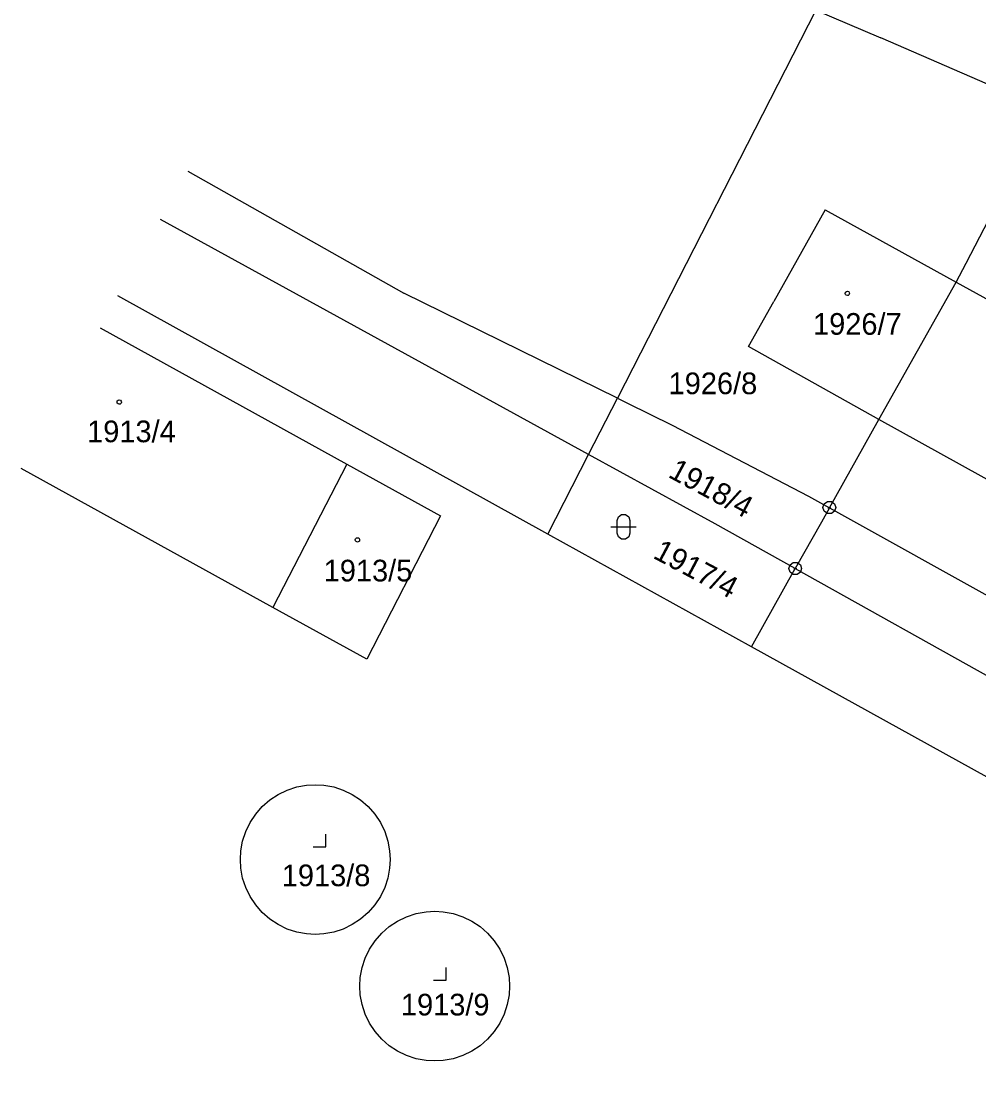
# Model space of a CAD drawing. Extents: x -528274 to -527531, y -1079304 to -1078580.
# Drawn here: x -528058.5 to -527983.4, y -1078819.1 to -1078735.9 of the extents above; entities that cross this region are included whole.
import ezdxf

# ---------------------------------------------------------------- set-up
doc = ezdxf.new("R2010")
doc.units = 0
doc.layers.add('katastrální mapa', color=7, linetype='Continuous')

msp = doc.modelspace()

# ---------------------------------------------------------------- linework, layer by layer
at = {"layer": 'katastrální mapa'}
for p, q in [((-527996.14, -1078735.08), (-528011.72, -1078765.52)), ((-527996.14, -1078735.08), (-527991.06, -1078737.26)), ((-527978.3, -1078742.81), (-527991.06, -1078737.26)), ((-528045.427, -1078747.725), (-528028.47, -1078757.28)), ((-527984.36, -1078754.92), (-527981.87, -1078750.15)), ((-527995.41, -1078750.75), (-527999.45, -1078757.94)), ((-527995.41, -1078750.75), (-527985.15, -1078756.42)), ((-528013.97, -1078769.93), (-528047.547, -1078751.51)), ((-527985.15, -1078756.42), (-527984.36, -1078754.92)), ((-527991.2, -1078767.2), (-527985.15, -1078756.42)), ((-527985.15, -1078756.42), (-527971.57, -1078763.89)), ((-528017.17, -1078776.18), (-528050.904, -1078757.504)), ((-528011.72, -1078765.52), (-528028.47, -1078757.28)), ((-528001.44, -1078761.48), (-527999.45, -1078757.94)), ((-528052.305, -1078760.006), (-528032.94, -1078770.7)), ((-527991.2, -1078767.2), (-528001.44, -1078761.48)), ((-528013.97, -1078769.93), (-528011.72, -1078765.52)), ((-528011.72, -1078765.52), (-528010.91, -1078765.92)), ((-528010.91, -1078765.92), (-528007.43, -1078767.64)), ((-527995.08, -1078774.12), (-527991.2, -1078767.2)), ((-527977.61, -1078774.72), (-527991.2, -1078767.2)), ((-528007.43, -1078767.64), (-527996.71, -1078773.21)), ((-528017.17, -1078776.18), (-528013.97, -1078769.93)), ((-528004.05, -1078775.37), (-528013.97, -1078769.93)), ((-528038.74, -1078781.95), (-528058.488, -1078771.047)), ((-528032.94, -1078770.7), (-528038.74, -1078781.95)), ((-528032.94, -1078770.7), (-528025.59, -1078774.75)), ((-527996.71, -1078773.21), (-527995.08, -1078774.12)), ((-527995.08, -1078774.12), (-527995.71, -1078775.24)), ((-527995.2, -1078774.12), (-527994.96, -1078774.12)), ((-527995.08, -1078774.12), (-527926.64, -1078812.22)), ((-528025.59, -1078774.75), (-528031.36, -1078786)), ((-527997.76, -1078778.89), (-528004.05, -1078775.37)), ((-527995.71, -1078775.24), (-527997.76, -1078778.89)), ((-528001.2, -1078785.02), (-528017.17, -1078776.18)), ((-528001.2, -1078785.02), (-527997.76, -1078778.89)), ((-527997.88, -1078778.89), (-527997.64, -1078778.89)), ((-527997.76, -1078778.89), (-527934.62, -1078814.19)), ((-528031.36, -1078786), (-528038.74, -1078781.95)), ((-527931.92, -1078823.37), (-528001.2, -1078785.02))]:
    msp.add_line(p, q, dxfattribs=at)
for points in [[(-527993.67, -1078757.14), (-527993.57, -1078757.16), (-527993.52, -1078757.25), (-527993.5, -1078757.31), (-527993.52, -1078757.4), (-527993.6, -1078757.47), (-527993.67, -1078757.48), (-527993.76, -1078757.45), (-527993.82, -1078757.39), (-527993.84, -1078757.31), (-527993.82, -1078757.22), (-527993.74, -1078757.15)], [(-528050.8, -1078765.66), (-528050.7, -1078765.68), (-528050.65, -1078765.77), (-528050.63, -1078765.83), (-528050.65, -1078765.92), (-528050.73, -1078765.99), (-528050.8, -1078766), (-528050.89, -1078765.97), (-528050.95, -1078765.91), (-528050.97, -1078765.83), (-528050.95, -1078765.74), (-528050.87, -1078765.67)], [(-527994.93, -1078773.64), (-527994.68, -1078773.82), (-527994.58, -1078774.11), (-527994.68, -1078774.4), (-527994.93, -1078774.58), (-527995.24, -1078774.58), (-527995.49, -1078774.4), (-527995.59, -1078774.11), (-527995.49, -1078773.82), (-527995.24, -1078773.64)], [(-528011.74, -1078775.12), (-528011.64, -1078774.83), (-528011.39, -1078774.65), (-528011.08, -1078774.65), (-528010.83, -1078774.83), (-528010.73, -1078775.12), (-528010.73, -1078776.12), (-528010.83, -1078776.41), (-528011.08, -1078776.59), (-528011.39, -1078776.59), (-528011.64, -1078776.41), (-528011.74, -1078776.12)], [(-528032.11, -1078776.47), (-528032.01, -1078776.49), (-528031.96, -1078776.58), (-528031.94, -1078776.64), (-528031.96, -1078776.73), (-528032.04, -1078776.8), (-528032.11, -1078776.81), (-528032.2, -1078776.78), (-528032.26, -1078776.72), (-528032.28, -1078776.64), (-528032.26, -1078776.55), (-528032.18, -1078776.48)], [(-527997.61, -1078778.41), (-527997.36, -1078778.59), (-527997.26, -1078778.88), (-527997.36, -1078779.17), (-527997.61, -1078779.35), (-527997.92, -1078779.35), (-527998.17, -1078779.17), (-527998.27, -1078778.88), (-527998.17, -1078778.59), (-527997.92, -1078778.41)]]:
    msp.add_lwpolyline(points, close=True, dxfattribs=at)
for points in [[(-528012.24, -1078775.62), (-528010.97, -1078775.62), (-528010.24, -1078775.62)], [(-528035.42, -1078807.59), (-528036.099, -1078807.557), (-528036.872, -1078807.414), (-528037.62, -1078807.169), (-528038.328, -1078806.827), (-528038.983, -1078806.393), (-528039.575, -1078805.875), (-528040.093, -1078805.283), (-528040.527, -1078804.628), (-528040.869, -1078803.92), (-528041.114, -1078803.172), (-528041.257, -1078802.399), (-528041.29, -1078801.72), (-528041.257, -1078801.041), (-528041.114, -1078800.268), (-528040.869, -1078799.52), (-528040.527, -1078798.812), (-528040.093, -1078798.157), (-528039.575, -1078797.565), (-528038.983, -1078797.047), (-528038.328, -1078796.613), (-528037.62, -1078796.271), (-528036.872, -1078796.026), (-528036.099, -1078795.883), (-528035.42, -1078795.85)], [(-528035.42, -1078795.85), (-528034.741, -1078795.883), (-528033.968, -1078796.026), (-528033.22, -1078796.271), (-528032.512, -1078796.613), (-528031.857, -1078797.047), (-528031.265, -1078797.565), (-528030.747, -1078798.157), (-528030.313, -1078798.812), (-528029.971, -1078799.52), (-528029.726, -1078800.268), (-528029.583, -1078801.041), (-528029.55, -1078801.72), (-528029.583, -1078802.399), (-528029.726, -1078803.172), (-528029.971, -1078803.92), (-528030.313, -1078804.628), (-528030.747, -1078805.283), (-528031.265, -1078805.875), (-528031.857, -1078806.393), (-528032.512, -1078806.827), (-528033.22, -1078807.169), (-528033.968, -1078807.414), (-528034.741, -1078807.557), (-528035.42, -1078807.59)], [(-528035.58, -1078800.73), (-528034.58, -1078800.73), (-528034.58, -1078799.73)], [(-528026.05, -1078817.52), (-528026.729, -1078817.487), (-528027.502, -1078817.344), (-528028.25, -1078817.099), (-528028.958, -1078816.757), (-528029.613, -1078816.323), (-528030.205, -1078815.805), (-528030.723, -1078815.213), (-528031.157, -1078814.558), (-528031.499, -1078813.85), (-528031.744, -1078813.102), (-528031.887, -1078812.329), (-528031.92, -1078811.65), (-528031.887, -1078810.971), (-528031.744, -1078810.198), (-528031.499, -1078809.45), (-528031.157, -1078808.742), (-528030.723, -1078808.087), (-528030.205, -1078807.495), (-528029.613, -1078806.977), (-528028.958, -1078806.543), (-528028.25, -1078806.201), (-528027.502, -1078805.956), (-528026.729, -1078805.813), (-528026.05, -1078805.78)], [(-528026.05, -1078805.78), (-528025.371, -1078805.813), (-528024.598, -1078805.956), (-528023.85, -1078806.201), (-528023.142, -1078806.543), (-528022.487, -1078806.977), (-528021.895, -1078807.495), (-528021.377, -1078808.087), (-528020.943, -1078808.742), (-528020.601, -1078809.45), (-528020.356, -1078810.198), (-528020.213, -1078810.971), (-528020.18, -1078811.65), (-528020.213, -1078812.329), (-528020.356, -1078813.102), (-528020.601, -1078813.85), (-528020.943, -1078814.558), (-528021.377, -1078815.213), (-528021.895, -1078815.805), (-528022.487, -1078816.323), (-528023.142, -1078816.757), (-528023.85, -1078817.099), (-528024.598, -1078817.344), (-528025.371, -1078817.487), (-528026.05, -1078817.52)], [(-528026.15, -1078811.18), (-528025.15, -1078811.18), (-528025.15, -1078810.18)]]:
    msp.add_lwpolyline(points, dxfattribs=at)

# ---------------------------------------------------------------- texts
for s, p in [('1926/7', (-527996.367, -1078760.55)), ('1926/8', (-528007.697, -1078765.21)), ('1913/4', (-528053.317, -1078768.98)), ('1913/5', (-528034.757, -1078779.9)), ('1913/8', (-528038.047, -1078803.81)), ('1913/9', (-528028.697, -1078813.95))]:
    msp.add_text(s, height=1.7, dxfattribs=at).set_placement(p)
for s, rotation, p in [('1918/4', 331.68527, (-528007.814, -1078771.676)), ('1917/4', 332.02904, (-528009.003, -1078778.024))]:
    msp.add_text(s, height=1.7, rotation=rotation, dxfattribs=at).set_placement(p)

doc.saveas('drawing.dxf')
